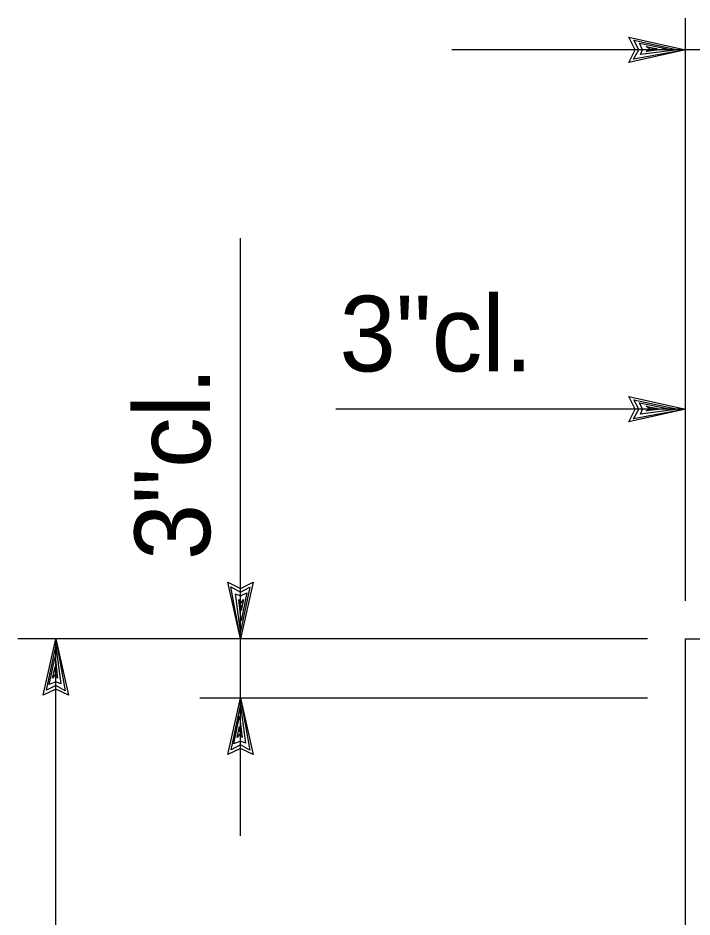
# Model space of a CAD drawing. Extents: x -0.08 to 2.83, y -0.03 to 1.92.
# Drawn here: x 1.6451 to 1.7611, y 0.3296 to 0.4843 of the extents above; entities that cross this region are included whole.
import ezdxf

# ---------------------------------------------------------------- set-up
doc = ezdxf.new("R2010")
doc.units = 0
for name, color, linetype in [('50', 7, 'Continuous'), ('55', 7, 'Continuous'), ('57', 7, 'Continuous')]:
    doc.layers.add(name, color=color, linetype=linetype)

msp = doc.modelspace()

# ---------------------------------------------------------------- linework, layer by layer
at = {"layer": '50'}
for p, q in [((1.75992, 0.37752), (1.79058, 0.37752)), ((1.75992, 0.21401), (1.75992, 0.37752))]:
    msp.add_line(p, q, dxfattribs=at)
at = {"layer": '55'}
for p, q in [((1.75992, 0.38403), (1.75992, 0.48434)), ((1.75127, 0.47889), (1.75021, 0.48106)), ((1.75021, 0.48106), (1.75992, 0.47889)), ((1.7519, 0.47889), (1.75106, 0.4805)), ((1.75106, 0.4805), (1.75865, 0.47889)), ((1.75253, 0.47889), (1.75204, 0.48)), ((1.75204, 0.48), (1.75682, 0.47902)), ((1.75992, 0.47889), (1.71971, 0.47889)), ((1.75992, 0.47889), (1.75021, 0.47669)), ((1.75021, 0.47669), (1.75127, 0.47889)), ((1.75992, 0.47889), (1.75098, 0.47726)), ((1.75098, 0.47726), (1.7519, 0.47889)), ((1.75865, 0.47889), (1.75218, 0.47804)), ((1.75218, 0.47804), (1.75253, 0.47889)), ((1.75387, 0.47895), (1.75317, 0.47944)), ((1.75317, 0.47944), (1.75507, 0.47902)), ((1.75682, 0.47902), (1.75317, 0.47859)), ((1.75317, 0.47859), (1.75387, 0.47895)), ((1.75507, 0.47902), (1.75415, 0.47902)), ((1.79058, 0.47889), (1.75992, 0.47889)), ((1.68334, 0.34363), (1.68334, 0.44645)), ((1.75127, 0.41701), (1.75021, 0.41919)), ((1.75021, 0.41919), (1.75992, 0.41701)), ((1.7519, 0.41701), (1.75106, 0.41863)), ((1.75106, 0.41863), (1.75865, 0.41701)), ((1.75253, 0.41701), (1.75204, 0.41813)), ((1.75204, 0.41813), (1.75682, 0.41715)), ((1.75992, 0.41701), (1.69976, 0.41701)), ((1.75992, 0.41701), (1.75021, 0.41482)), ((1.75021, 0.41482), (1.75127, 0.41701)), ((1.75992, 0.41701), (1.75098, 0.41539)), ((1.75098, 0.41539), (1.7519, 0.41701)), ((1.75865, 0.41701), (1.75218, 0.41617)), ((1.75218, 0.41617), (1.75253, 0.41701)), ((1.75387, 0.41708), (1.75317, 0.41757)), ((1.75317, 0.41757), (1.75507, 0.41715)), ((1.75682, 0.41715), (1.75317, 0.41672)), ((1.75317, 0.41672), (1.75387, 0.41708)), ((1.75507, 0.41715), (1.75415, 0.41715)), ((1.68334, 0.37752), (1.68115, 0.38723)), ((1.68115, 0.38723), (1.68334, 0.38617)), ((1.68334, 0.38617), (1.68551, 0.38723)), ((1.68551, 0.38723), (1.68334, 0.37752)), ((1.68334, 0.37752), (1.68171, 0.38645)), ((1.68171, 0.38645), (1.68334, 0.38554)), ((1.68334, 0.37878), (1.68249, 0.38526)), ((1.68249, 0.38526), (1.68334, 0.38491)), ((1.68334, 0.38554), (1.68495, 0.38638)), ((1.68495, 0.38638), (1.68334, 0.37878)), ((1.68334, 0.38491), (1.68446, 0.3854)), ((1.68446, 0.3854), (1.68347, 0.38061)), ((1.68347, 0.38061), (1.68304, 0.38427)), ((1.68304, 0.38427), (1.6834, 0.38357)), ((1.6834, 0.38357), (1.68389, 0.38427)), ((1.68389, 0.38427), (1.68347, 0.38237)), ((1.68347, 0.38237), (1.68347, 0.38329)), ((1.75341, 0.37752), (1.64505, 0.37752)), ((1.64939, 0.36781), (1.65156, 0.37752)), ((1.65156, 0.21401), (1.65156, 0.37752)), ((1.65156, 0.37752), (1.65376, 0.36781)), ((1.65156, 0.37752), (1.65319, 0.36858)), ((1.64995, 0.36865), (1.65156, 0.37625)), ((1.65156, 0.37625), (1.65241, 0.36977)), ((1.65045, 0.36963), (1.65143, 0.37442)), ((1.65143, 0.37442), (1.65186, 0.37076)), ((1.65101, 0.37076), (1.65143, 0.37266)), ((1.6515, 0.37146), (1.65101, 0.37076)), ((1.65143, 0.37266), (1.65143, 0.37174)), ((1.65186, 0.37076), (1.6515, 0.37146)), ((1.65156, 0.37013), (1.65045, 0.36963)), ((1.65241, 0.36977), (1.65156, 0.37013)), ((1.65156, 0.36886), (1.64939, 0.36781)), ((1.65156, 0.3695), (1.64995, 0.36865)), ((1.65319, 0.36858), (1.65156, 0.3695)), ((1.65376, 0.36781), (1.65156, 0.36886)), ((1.75341, 0.3673), (1.67636, 0.3673)), ((1.68116, 0.35759), (1.68334, 0.3673)), ((1.68334, 0.3673), (1.68553, 0.35759)), ((1.68334, 0.3673), (1.68496, 0.35836)), ((1.68172, 0.35843), (1.68334, 0.36603)), ((1.68334, 0.36603), (1.68419, 0.35955)), ((1.68222, 0.35941), (1.6832, 0.3642)), ((1.6832, 0.3642), (1.68363, 0.36054)), ((1.68279, 0.36054), (1.6832, 0.36244)), ((1.6832, 0.36244), (1.6832, 0.36152)), ((1.68327, 0.36124), (1.68279, 0.36054)), ((1.68363, 0.36054), (1.68327, 0.36124)), ((1.68334, 0.35928), (1.68172, 0.35843)), ((1.68334, 0.35991), (1.68222, 0.35941)), ((1.68419, 0.35955), (1.68334, 0.35991)), ((1.68496, 0.35836), (1.68334, 0.35928)), ((1.68334, 0.35864), (1.68116, 0.35759)), ((1.68553, 0.35759), (1.68334, 0.35864))]:
    msp.add_line(p, q, dxfattribs=at)

# ---------------------------------------------------------------- texts
at = {"layer": '57'}
msp.add_text('3"cl.', height=0.013021, dxfattribs=at).set_placement((1.70039, 0.42353))
msp.add_text('3"cl.', height=0.013021, rotation=90, dxfattribs=at).set_placement((1.67813, 0.39105))

doc.saveas('drawing.dxf')
